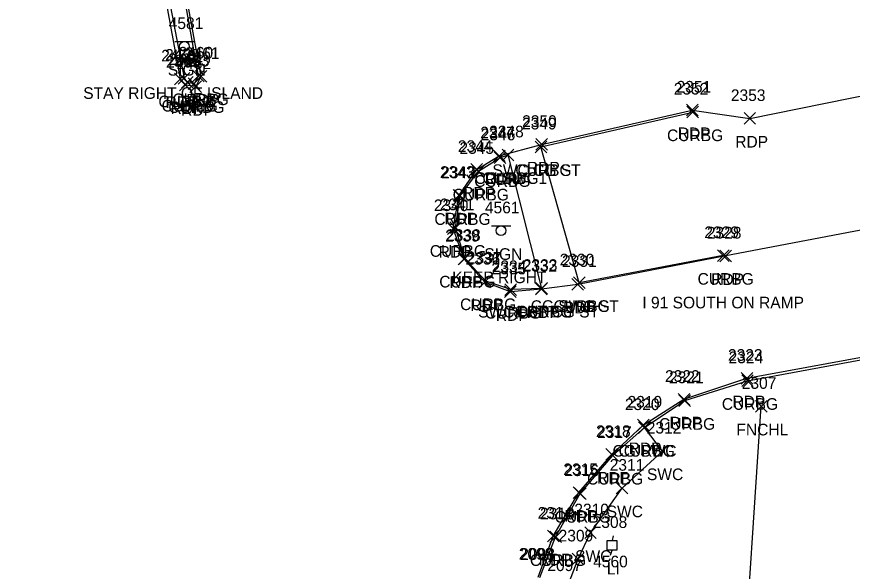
# Model space of a CAD drawing. Extents: x 1690689 to 1696275, y 438760 to 444007.
# Drawn here: x 1691375.5 to 1691519.2, y 440321.4 to 440416.7 of the extents above; entities that cross this region are included whole.
import ezdxf

# ---------------------------------------------------------------- set-up
doc = ezdxf.new("R2010")
doc.units = 0
for name, color, linetype in [('L_A', 7, 'Continuous'), ('L_I', 7, 'Continuous'), ('L_TIC', 7, 'Continuous'), ('LFNC', 7, 'Continuous'), ('P_A', 7, 'Continuous'), ('P_C', 7, 'Continuous'), ('P_I', 7, 'Continuous'), ('P_TIC', 7, 'Continuous'), ('PET', 7, 'Continuous'), ('R_A', 7, 'Continuous'), ('R_I', 7, 'Continuous'), ('R_TIC', 7, 'Continuous'), ('RC', 7, 'Continuous'), ('RSW', 7, 'Continuous'), ('S_A', 7, 'Continuous'), ('S_C', 7, 'Continuous'), ('S_I', 7, 'Continuous'), ('SSGN', 7, 'Continuous'), ('U_A', 7, 'Continuous'), ('U_I', 7, 'Continuous'), ('ULP', 7, 'Continuous')]:
    doc.layers.add(name, color=color, linetype=linetype)

msp = doc.modelspace()

# ---------------------------------------------------------------- linework, layer by layer
at = {"layer": 'L_TIC'}
for points in [[(1691502.51, 440348.74), (1691504.51, 440350.74)], [(1691504.51, 440348.74), (1691502.51, 440350.74)]]:
    msp.add_lwpolyline(points, dxfattribs=at)
at = {"layer": 'LFNC'}
msp.add_lwpolyline([(1691807.26, 439412.53), (1691787.48, 439430.41), (1691771.88, 439447.07), (1691690.47, 439555.17), (1691645.43, 439634.56), (1691611.1, 439707.77), (1691582.01, 439789.5), (1691566.71, 439848.94), (1691556.2, 439899.11), (1691546, 439958.42), (1691528.18, 440069.26), (1691515.01, 440157.78), (1691504.49, 440231.44), (1691500.26, 440300.18), (1691503.51, 440349.74)], dxfattribs=at)
at = {"layer": 'P_TIC'}
for points in [[(1691402.64, 440404.97), (1691404.64, 440406.97)], [(1691404.64, 440404.97), (1691402.64, 440406.97)], [(1691406.2, 440405.4), (1691408.2, 440407.4)], [(1691408.2, 440405.4), (1691406.2, 440407.4)], [(1691403.52, 440403.92), (1691405.52, 440405.92)], [(1691405.52, 440403.92), (1691403.52, 440405.92)], [(1691403.52, 440403.92), (1691405.52, 440405.92)], [(1691405.52, 440403.92), (1691403.52, 440405.92)], [(1691405.31, 440403.65), (1691407.31, 440405.65)], [(1691407.31, 440403.65), (1691405.31, 440405.65)], [(1691490.67, 440399.63), (1691492.67, 440401.63)], [(1691492.67, 440399.63), (1691490.67, 440401.63)], [(1691500.56, 440398.18), (1691502.56, 440400.18)], [(1691502.56, 440398.18), (1691500.56, 440400.18)], [(1691464.77, 440393.73), (1691466.77, 440395.73)], [(1691466.77, 440393.73), (1691464.77, 440395.73)], [(1691457.48, 440391.76), (1691459.48, 440393.76)], [(1691459.48, 440391.76), (1691457.48, 440393.76)], [(1691453.63, 440389.43), (1691455.63, 440391.43)], [(1691455.63, 440389.43), (1691453.63, 440391.43)], [(1691450.57, 440384.98), (1691452.57, 440386.98)], [(1691452.57, 440384.98), (1691450.57, 440386.98)], [(1691449.59, 440379.27), (1691451.59, 440381.27)], [(1691451.59, 440379.27), (1691449.59, 440381.27)], [(1691496.43, 440374.56), (1691498.43, 440376.56)], [(1691498.43, 440374.56), (1691496.43, 440376.56)], [(1691451.44, 440374.04), (1691453.44, 440376.04)], [(1691453.44, 440374.04), (1691451.44, 440376.04)], [(1691455.01, 440370.09), (1691457.01, 440372.09)], [(1691457.01, 440370.09), (1691455.01, 440372.09)], [(1691464.73, 440368.88), (1691466.73, 440370.88)], [(1691466.73, 440368.88), (1691464.73, 440370.88)], [(1691470.98, 440369.69), (1691472.98, 440371.69)], [(1691472.98, 440369.69), (1691470.98, 440371.69)], [(1691459.4, 440368.42), (1691461.4, 440370.42)], [(1691461.4, 440368.42), (1691459.4, 440370.42)], [(1691500.06, 440353.56), (1691502.06, 440355.56)], [(1691502.06, 440353.56), (1691500.06, 440355.56)], [(1691489.24, 440349.94), (1691491.24, 440351.94)], [(1691491.24, 440349.94), (1691489.24, 440351.94)], [(1691482.24, 440345.52), (1691484.24, 440347.52)], [(1691484.24, 440345.52), (1691482.24, 440347.52)], [(1691476.82, 440340.47), (1691478.82, 440342.47)], [(1691478.82, 440340.47), (1691476.82, 440342.47)], [(1691471.19, 440333.92), (1691473.19, 440335.92)], [(1691473.19, 440333.92), (1691471.19, 440335.92)], [(1691466.78, 440326.44), (1691468.78, 440328.44)], [(1691468.78, 440326.44), (1691466.78, 440328.44)]]:
    msp.add_lwpolyline(points, dxfattribs=at)
at = {"layer": 'PET'}
for points in [[(1691327.11, 440842.3), (1691343.83, 440752.44), (1691362.78, 440649.9), (1691372.44, 440596.72), (1691388.92, 440507.28), (1691399.19, 440450.17), (1691407.2, 440406.4), (1691406.31, 440404.65), (1691404.52, 440404.92)], [(1691315.38, 440840.77), (1691339.16, 440752.24), (1691344.67, 440727.73), (1691359.12, 440649.27), (1691368.01, 440600.75), (1691385.38, 440506.23), (1691396.38, 440445.66), (1691403.64, 440405.97), (1691404.52, 440404.92)], [(1691562.26, 440387.89), (1691497.43, 440375.56), (1691471.98, 440370.69), (1691465.73, 440369.88), (1691460.4, 440369.42), (1691456.01, 440371.09), (1691452.44, 440375.04), (1691450.59, 440380.27), (1691451.57, 440385.98), (1691454.63, 440390.43), (1691458.48, 440392.76), (1691465.77, 440394.73), (1691491.67, 440400.63), (1691501.56, 440399.18), (1691557.23, 440410.45)], [(1691465.2, 440320.4), (1691467.78, 440327.44), (1691472.19, 440334.92), (1691477.82, 440341.47), (1691483.24, 440346.52), (1691490.24, 440350.94), (1691501.06, 440354.56), (1691566.38, 440366.53)]]:
    msp.add_lwpolyline(points, dxfattribs=at)
at = {"layer": 'R_TIC'}
for points in [[(1691403.32, 440405.1), (1691405.32, 440407.1)], [(1691405.32, 440405.1), (1691403.32, 440407.1)], [(1691405.75, 440405.47), (1691407.75, 440407.47)], [(1691407.75, 440405.47), (1691405.75, 440407.47)], [(1691403.87, 440404.37), (1691405.87, 440406.37)], [(1691405.87, 440404.37), (1691403.87, 440406.37)], [(1691403.87, 440404.37), (1691405.87, 440406.37)], [(1691405.87, 440404.37), (1691403.87, 440406.37)], [(1691405.03, 440404.14), (1691407.03, 440406.14)], [(1691407.03, 440404.14), (1691405.03, 440406.14)], [(1691490.74, 440399.29), (1691492.74, 440401.29)], [(1691492.74, 440399.29), (1691490.74, 440401.29)], [(1691464.66, 440393.3), (1691466.66, 440395.3)], [(1691466.66, 440393.3), (1691464.66, 440395.3)], [(1691464.66, 440393.3), (1691466.66, 440395.3)], [(1691466.66, 440393.3), (1691464.66, 440395.3)], [(1691459.01, 440391.93), (1691461.01, 440393.93)], [(1691461.01, 440391.93), (1691459.01, 440393.93)], [(1691459.01, 440391.93), (1691461.01, 440393.93)], [(1691461.01, 440391.93), (1691459.01, 440393.93)], [(1691457.61, 440391.43), (1691459.61, 440393.43)], [(1691459.61, 440391.43), (1691457.61, 440393.43)], [(1691453.9, 440389.1), (1691455.9, 440391.1)], [(1691455.9, 440389.1), (1691453.9, 440391.1)], [(1691450.76, 440384.9), (1691452.76, 440386.9)], [(1691452.76, 440384.9), (1691450.76, 440386.9)], [(1691449.97, 440379.42), (1691451.97, 440381.42)], [(1691451.97, 440379.42), (1691449.97, 440381.42)], [(1691496, 440374.63), (1691498, 440376.63)], [(1691498, 440374.63), (1691496, 440376.63)], [(1691451.6, 440374.15), (1691453.6, 440376.15)], [(1691453.6, 440374.15), (1691451.6, 440376.15)], [(1691455.18, 440370.26), (1691457.18, 440372.26)], [(1691457.18, 440370.26), (1691455.18, 440372.26)], [(1691459.46, 440368.8), (1691461.46, 440370.8)], [(1691461.46, 440368.8), (1691459.46, 440370.8)], [(1691464.8, 440369), (1691466.8, 440371)], [(1691466.8, 440369), (1691464.8, 440371)], [(1691464.8, 440369), (1691466.8, 440371)], [(1691466.8, 440369), (1691464.8, 440371)], [(1691471.23, 440369.95), (1691473.23, 440371.95)], [(1691473.23, 440369.95), (1691471.23, 440371.95)], [(1691471.23, 440369.95), (1691473.23, 440371.95)], [(1691473.23, 440369.95), (1691471.23, 440371.95)], [(1691500.16, 440353.14), (1691502.16, 440355.14)], [(1691502.16, 440353.14), (1691500.16, 440355.14)], [(1691489.37, 440349.71), (1691491.37, 440351.71)], [(1691491.37, 440349.71), (1691489.37, 440351.71)], [(1691482.43, 440345.09), (1691484.43, 440347.09)], [(1691484.43, 440345.09), (1691482.43, 440347.09)], [(1691482.43, 440345.09), (1691484.43, 440347.09)], [(1691484.43, 440345.09), (1691482.43, 440347.09)], [(1691476.99, 440340.3), (1691478.99, 440342.3)], [(1691478.99, 440340.3), (1691476.99, 440342.3)], [(1691485.52, 440341.06), (1691487.52, 440343.06)], [(1691487.52, 440341.06), (1691485.52, 440343.06)], [(1691478.59, 440334.68), (1691480.59, 440336.68)], [(1691480.59, 440334.68), (1691478.59, 440336.68)], [(1691471.42, 440333.75), (1691473.42, 440335.75)], [(1691473.42, 440333.75), (1691471.42, 440335.75)], [(1691467.18, 440326.32), (1691469.18, 440328.32)], [(1691469.18, 440326.32), (1691467.18, 440328.32)], [(1691473.17, 440327.01), (1691475.17, 440329.01)], [(1691475.17, 440327.01), (1691473.17, 440329.01)], [(1691471.04, 440322.53), (1691473.04, 440324.53)], [(1691473.04, 440322.53), (1691471.04, 440324.53)]]:
    msp.add_lwpolyline(points, dxfattribs=at)
at = {"layer": 'RC'}
for points in [[(1691326.44, 440842.32), (1691343.27, 440752.33), (1691362.34, 440649.71), (1691372.07, 440596.75), (1691388.57, 440507.07), (1691399.02, 440450.03), (1691406.75, 440406.47), (1691406.03, 440405.14), (1691404.87, 440405.37)], [(1691369.88, 440592.69), (1691385.96, 440506.35), (1691395.57, 440453.11), (1691397.57, 440451.5), (1691398.07, 440448.42), (1691396.76, 440445.61), (1691404.32, 440406.1), (1691404.87, 440405.37)], [(1691465.66, 440394.3), (1691491.74, 440400.29)], [(1691465.8, 440370), (1691460.46, 440369.8), (1691456.18, 440371.26), (1691452.6, 440375.15), (1691450.97, 440380.42), (1691451.76, 440385.9), (1691454.9, 440390.1), (1691458.61, 440392.43), (1691460.01, 440392.93)], [(1691497, 440375.63), (1691472.23, 440370.95)], [(1691465.44, 440320.36), (1691468.18, 440327.32), (1691472.42, 440334.75), (1691477.99, 440341.3), (1691483.43, 440346.09), (1691490.37, 440350.71), (1691501.16, 440354.14), (1691566.4, 440366.17)]]:
    msp.add_lwpolyline(points, dxfattribs=at)
at = {"layer": 'RSW'}
for points in [[(1691472.23, 440370.95), (1691465.66, 440394.3)], [(1691465.8, 440370), (1691460.01, 440392.93)], [(1691470.09, 440318.44), (1691472.04, 440323.53), (1691474.17, 440328.01), (1691479.59, 440335.68), (1691486.52, 440342.06), (1691483.43, 440346.09)]]:
    msp.add_lwpolyline(points, dxfattribs=at)
at = {"layer": 'SSGN'}
for p, q in [((1691402.73, 440412.39), (1691406.07, 440412.39)), ((1691404.38, 440411.56), (1691404.38, 440411.56)), ((1691457.13, 440380.74), (1691460.46, 440380.74)), ((1691458.78, 440379.91), (1691458.78, 440379.91))]:
    msp.add_line(p, q, dxfattribs=at)
for centre in [(1691404.38, 440411.56), (1691458.78, 440379.91)]:
    msp.add_circle(centre, 0.833, dxfattribs=at)
at = {"layer": 'ULP'}
for p, q in [((1691477.04, 440325.02), (1691477.04, 440326.69)), ((1691477.04, 440326.69), (1691478.71, 440326.69)), ((1691478.04, 440327.52), (1691477.88, 440326.69)), ((1691478.71, 440326.69), (1691478.71, 440325.02)), ((1691478.71, 440325.02), (1691477.04, 440325.02)), ((1691477.63, 440324.19), (1691477.88, 440325.02)), ((1691477.88, 440325.85), (1691477.88, 440325.85))]:
    msp.add_line(p, q, dxfattribs=at)

# ---------------------------------------------------------------- texts
at = {"layer": 'L_A'}
msp.add_text('FNCHL', height=2, dxfattribs=at).set_placement((1691499.25, 440344.74))
at = {"layer": 'L_I'}
msp.add_text('2307', height=2, dxfattribs=at).set_placement((1691500.17, 440352.74))
at = {"layer": 'P_A'}
for p in [(1691401.13, 440400.97), (1691404.69, 440401.4), (1691402.01, 440399.92), (1691402.01, 440399.92), (1691403.8, 440399.65), (1691489.16, 440395.63), (1691499.05, 440394.18), (1691463.25, 440389.73), (1691455.97, 440387.76), (1691452.12, 440385.43), (1691449.06, 440380.98), (1691448.08, 440375.27), (1691494.92, 440370.56), (1691449.93, 440370.04), (1691453.5, 440366.09), (1691463.22, 440364.88), (1691469.46, 440365.69), (1691457.89, 440364.42), (1691498.55, 440349.56), (1691487.73, 440345.94), (1691480.73, 440341.52), (1691475.3, 440336.47), (1691469.68, 440329.92), (1691465.27, 440322.44)]:
    msp.add_text('RDP', height=2, dxfattribs=at).set_placement(p)
at = {"layer": 'P_C'}
msp.add_text('I 91 SOUTH ON RAMP', height=2, dxfattribs=at).set_placement((1691483.08, 440366.56))
at = {"layer": 'P_I'}
for s, p in [('2458', (1691400.38, 440408.97)), ('2461', (1691404.46, 440409.4)), ('2465', (1691401.21, 440407.92)), ('2465', (1691401.21, 440407.92)), ('2462', (1691403, 440407.65)), ('2351', (1691488.97, 440403.63)), ('2353', (1691498.3, 440402.18)), ('2350', (1691462.42, 440397.73)), ('2347', (1691455.22, 440395.76)), ('2344', (1691451.37, 440393.43)), ('2343', (1691448.31, 440388.98)), ('2340', (1691447.24, 440383.27)), ('2339', (1691449.18, 440378.04)), ('2328', (1691494.17, 440378.56)), ('2336', (1691452.69, 440374.09)), ('2331', (1691469.28, 440373.69)), ('2335', (1691457.14, 440372.42)), ('2332', (1691462.47, 440372.88)), ('2323', (1691497.8, 440357.56)), ('2322', (1691486.98, 440353.94)), ('2319', (1691480.54, 440349.52)), ('2318', (1691475.12, 440344.47)), ('2315', (1691469.5, 440337.92)), ('2314', (1691465.09, 440330.44)), ('2099', (1691461.85, 440323.4))]:
    msp.add_text(s, height=2, dxfattribs=at).set_placement(p)
at = {"layer": 'R_A'}
for s, p in [('CURBG', (1691399.9, 440401.1)), ('CURBG', (1691400.45, 440400.37)), ('CURBG', (1691400.45, 440400.37)), ('CURBG', (1691402.33, 440401.47)), ('CURBG', (1691401.61, 440400.14)), ('CURBG', (1691487.33, 440395.29)), ('SWC CG ST', (1691457.32, 440389.3)), ('CURBG', (1691461.25, 440389.3)), ('CURBG', (1691454.19, 440387.43)), ('CG SWC1', (1691454.22, 440387.93)), ('CURBG', (1691455.6, 440387.93)), ('CURBG', (1691450.48, 440385.1)), ('CURBG', (1691447.34, 440380.9)), ('CURBG', (1691446.55, 440375.42)), ('CURBG', (1691448.18, 440370.15)), ('CURBG', (1691492.58, 440370.63)), ('CURBG', (1691451.76, 440366.26)), ('CG SWC ST', (1691463.89, 440365.95)), ('CURBG', (1691467.81, 440365.95)), ('SWC1 ST CG ST', (1691454.85, 440365)), ('CURBG', (1691456.05, 440364.8)), ('CURBG', (1691461.39, 440365)), ('CURBG', (1691496.75, 440349.14)), ('CURBG', (1691485.95, 440345.71)), ('CG SWC', (1691477.96, 440341.09)), ('CURBG', (1691479.01, 440341.09)), ('CURBG', (1691473.58, 440336.3)), ('SWC', (1691483.88, 440337.06)), ('SWC', (1691476.95, 440330.68)), ('CURBG', (1691468.01, 440329.75)), ('SWC', (1691471.53, 440323.01)), ('CURBG', (1691463.76, 440322.32))]:
    msp.add_text(s, height=2, dxfattribs=at).set_placement(p)
at = {"layer": 'R_I'}
for s, p in [('2459', (1691401.05, 440409.1)), ('2460', (1691403.36, 440409.47)), ('2464', (1691401.56, 440408.37)), ('2464', (1691401.56, 440408.37)), ('2463', (1691402.72, 440408.14)), ('2352', (1691488.48, 440403.29)), ('2349', (1691462.4, 440397.3)), ('2349', (1691462.4, 440397.3)), ('2346', (1691455.3, 440395.43)), ('2348', (1691456.75, 440395.93)), ('2348', (1691456.75, 440395.93)), ('2345', (1691451.64, 440393.1)), ('2342', (1691448.5, 440388.9)), ('2341', (1691448.28, 440383.42)), ('2338', (1691449.34, 440378.15)), ('2329', (1691493.73, 440378.63)), ('2337', (1691452.92, 440374.26)), ('2330', (1691468.88, 440373.95)), ('2330', (1691468.88, 440373.95)), ('2334', (1691457.2, 440372.8)), ('2333', (1691462.54, 440373)), ('2333', (1691462.54, 440373)), ('2324', (1691497.91, 440357.14)), ('2321', (1691487.67, 440353.71)), ('2320', (1691480.08, 440349.09)), ('2320', (1691480.08, 440349.09)), ('2317', (1691475.3, 440344.3)), ('2312', (1691483.83, 440345.06)), ('2311', (1691477.47, 440338.68)), ('2316', (1691469.68, 440337.75)), ('2313', (1691465.49, 440330.32)), ('2310', (1691471.39, 440331.01)), ('2309', (1691468.69, 440326.53)), ('2098', (1691462.1, 440323.36)), ('2098', (1691462.1, 440323.36)), ('2097', (1691466.75, 440321.44)), ('2097', (1691466.75, 440321.44))]:
    msp.add_text(s, height=2, dxfattribs=at).set_placement(p)
at = {"layer": 'S_A'}
for p in [(1691401.52, 440406.54), (1691455.92, 440374.89)]:
    msp.add_text('SIGN', height=2, dxfattribs=at).set_placement(p)
at = {"layer": 'S_C'}
for s, p in [('STAY RIGHT OF ISLAND', (1691386.98, 440402.54)), ('KEEP RIGHT', (1691450.4, 440370.89))]:
    msp.add_text(s, height=2, dxfattribs=at).set_placement(p)
at = {"layer": 'S_I'}
for s, p in [('4581', (1691401.67, 440414.54)), ('4561', (1691456.02, 440382.89)), ('4560', (1691474.63, 440322.08))]:
    msp.add_text(s, height=2, dxfattribs=at).set_placement(p)
at = {"layer": 'U_A'}
msp.add_text('LI', height=2, dxfattribs=at).set_placement((1691476.98, 440320.85))
at = {"layer": 'U_I'}
msp.add_text('2308', height=2, dxfattribs=at).set_placement((1691474.54, 440328.85))

doc.saveas('drawing.dxf')
